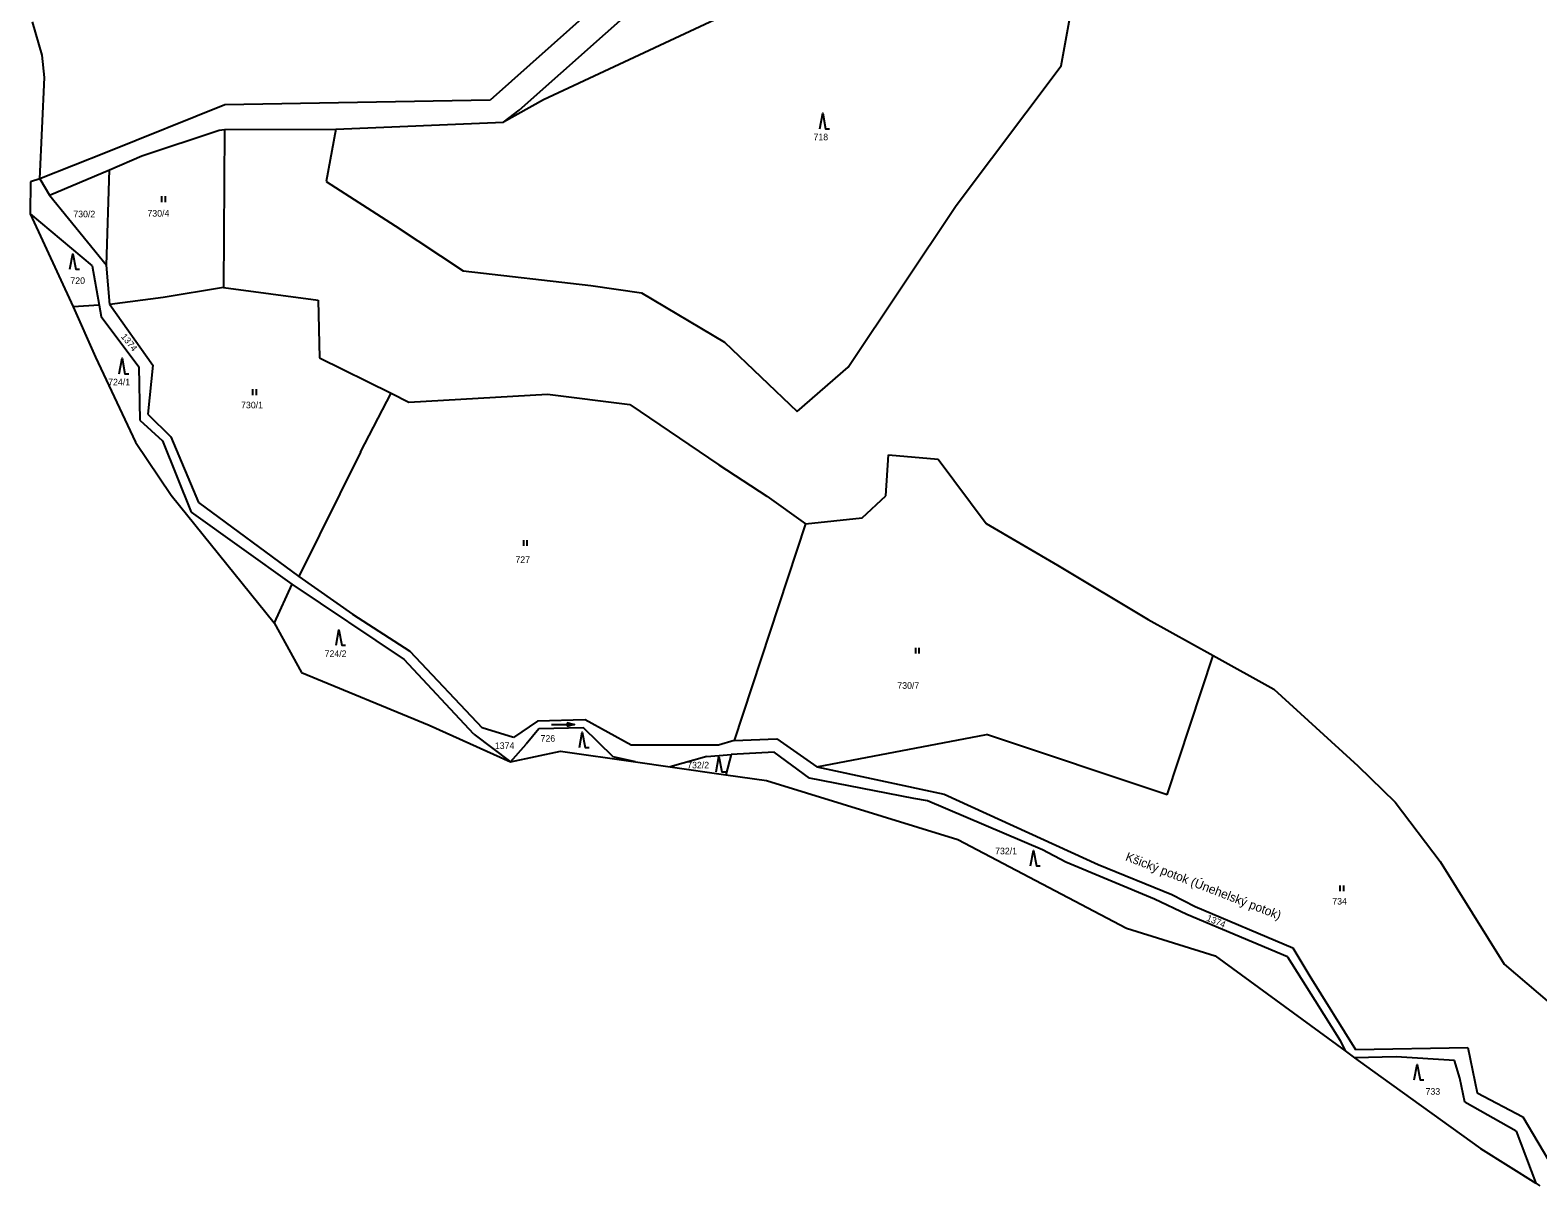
# Model space of a CAD drawing. Extents: x -845995 to -842497, y -1063614 to -1059680.
# Drawn here: x -845778.2 to -845387.3, y -1062481.6 to -1062182 of the extents above; entities that cross this region are included whole.
import ezdxf

# ---------------------------------------------------------------- set-up
doc = ezdxf.new("R2010")
doc.units = 0
for name, color, linetype in [('KN_HRANICE', 7, 'Continuous'), ('KN_KULTURY', 7, 'Continuous'), ('KN_PARCELY', 7, 'Continuous')]:
    doc.layers.add(name, color=color, linetype=linetype)

# ---------------------------------------------------------------- blocks, each defined once
blk = doc.blocks.new('306')
for p, q in [((-0.5, 1.5), (-0.5, 0)), ((0.5, 0), (0.5, 1.5))]:
    blk.add_line(p, q)
blk = doc.blocks.new('308')
blk.add_lwpolyline([(-0.75, 0), (0, 4), (0.75, 0), (1.75, 0)])
blk = doc.blocks.new('802')
blk.add_line((-3, 0), (3, 0))
blk.add_lwpolyline([(1, 0.5), (3, 0), (1, -0.5)])

msp = doc.modelspace()

# ---------------------------------------------------------------- linework, layer by layer
at = {"layer": 'KN_HRANICE'}
for p, q in [((-845510.92, -1062191.27), (-845498.56, -1062124.27)), ((-845651.42, -1062202.77), (-845618.23, -1062173.22)), ((-845585.39, -1062172.12), (-845645.11, -1062200.07)), ((-845632.82, -1062176.92), (-845658.96, -1062200.15)), ((-845775.06, -1062188.48), (-845777.6, -1062179.8)), ((-845774.46, -1062194.26), (-845775.06, -1062188.48)), ((-845775.65, -1062220.58), (-845774.46, -1062194.26)), ((-845538.14, -1062227.46), (-845510.92, -1062191.27)), ((-845727.72, -1062201.4), (-845758.25, -1062213.62)), ((-845658.96, -1062200.15), (-845727.72, -1062201.4)), ((-845645.11, -1062200.07), (-845655.45, -1062205.83)), ((-845698.95, -1062207.66), (-845655.45, -1062205.83)), ((-845655.45, -1062205.83), (-845651.42, -1062202.77)), ((-845749.23, -1062214.6), (-845729.21, -1062207.92)), ((-845729.21, -1062207.92), (-845727.82, -1062207.78)), ((-845727.82, -1062207.78), (-845728.1, -1062248.74)), ((-845727.82, -1062207.78), (-845698.95, -1062207.66)), ((-845698.95, -1062207.66), (-845701.42, -1062221.27)), ((-845758.25, -1062213.62), (-845775.65, -1062220.58)), ((-845757.67, -1062218.18), (-845749.23, -1062214.6)), ((-845778.11, -1062221.36), (-845778.2, -1062229.6)), ((-845775.65, -1062220.58), (-845778.11, -1062221.36)), ((-845775.65, -1062220.58), (-845773.15, -1062224.75)), ((-845773.15, -1062224.75), (-845757.67, -1062218.18)), ((-845758.41, -1062242.97), (-845757.67, -1062218.18)), ((-845701.42, -1062221.27), (-845683.57, -1062232.73)), ((-845773.15, -1062224.75), (-845758.41, -1062242.97)), ((-845778.2, -1062229.6), (-845767.01, -1062253.72)), ((-845778.2, -1062229.6), (-845762.16, -1062243.11)), ((-845566.08, -1062269.34), (-845538.14, -1062227.46)), ((-845683.57, -1062232.73), (-845665.91, -1062244.39)), ((-845762.16, -1062243.11), (-845760.29, -1062253.3)), ((-845757.58, -1062253.13), (-845758.41, -1062242.97)), ((-845665.91, -1062244.39), (-845632.86, -1062248.21)), ((-845728.1, -1062248.74), (-845743.72, -1062251.32)), ((-845728.1, -1062248.74), (-845703.56, -1062252.04)), ((-845632.86, -1062248.21), (-845619.68, -1062250.08)), ((-845743.72, -1062251.32), (-845757.58, -1062253.13)), ((-845757.58, -1062253.13), (-845746.37, -1062268.87)), ((-845703.56, -1062252.04), (-845703.22, -1062266.93)), ((-845619.68, -1062250.08), (-845598.19, -1062262.9)), ((-845760.29, -1062253.3), (-845767.01, -1062253.72)), ((-845767.01, -1062253.72), (-845761.26, -1062266.79)), ((-845760.29, -1062253.3), (-845759.76, -1062256.21)), ((-845759.76, -1062256.21), (-845750.05, -1062269.33)), ((-845598.19, -1062262.9), (-845579.34, -1062280.85)), ((-845761.26, -1062266.79), (-845750.91, -1062288.83)), ((-845746.37, -1062268.87), (-845747.73, -1062281.56)), ((-845703.22, -1062266.93), (-845684.57, -1062276.13)), ((-845750.05, -1062269.33), (-845749.77, -1062283.12)), ((-845579.34, -1062280.85), (-845566.08, -1062269.34)), ((-845692.53, -1062291.38), (-845684.57, -1062276.13)), ((-845684.57, -1062276.13), (-845680, -1062278.42)), ((-845680, -1062278.42), (-845644.04, -1062276.4)), ((-845644.04, -1062276.4), (-845622.69, -1062279.09)), ((-845622.69, -1062279.09), (-845599.61, -1062294.67)), ((-845749.77, -1062283.12), (-845743.88, -1062288.46)), ((-845747.73, -1062281.56), (-845741.76, -1062287.4)), ((-845741.76, -1062287.4), (-845734.56, -1062304.48)), ((-845750.91, -1062288.83), (-845741.6, -1062302.55)), ((-845743.88, -1062288.46), (-845736.47, -1062306.95)), ((-845692.53, -1062291.38), (-845708.51, -1062323.62)), ((-845556.32, -1062302.73), (-845555.68, -1062292.15)), ((-845555.68, -1062292.15), (-845542.82, -1062293.26)), ((-845599.61, -1062294.67), (-845587.21, -1062302.86)), ((-845542.82, -1062293.26), (-845530.36, -1062309.89)), ((-845741.6, -1062302.55), (-845714.94, -1062335.63)), ((-845587.21, -1062302.86), (-845577.18, -1062310.01)), ((-845562.49, -1062308.46), (-845556.32, -1062302.73)), ((-845736.47, -1062306.95), (-845710.33, -1062325.65)), ((-845734.56, -1062304.48), (-845708.51, -1062323.62)), ((-845577.18, -1062310.01), (-845595.64, -1062366.15)), ((-845577.18, -1062310.01), (-845562.49, -1062308.46)), ((-845530.36, -1062309.89), (-845511.8, -1062320.74)), ((-845511.8, -1062320.74), (-845488.37, -1062334.79)), ((-845710.33, -1062325.65), (-845714.94, -1062335.63)), ((-845710.33, -1062325.65), (-845681.19, -1062345.2)), ((-845708.51, -1062323.62), (-845694.59, -1062333.41)), ((-845694.59, -1062333.41), (-845679.72, -1062342.99)), ((-845488.37, -1062334.79), (-845471.52, -1062344.14)), ((-845714.94, -1062335.63), (-845707.89, -1062348.59)), ((-845679.72, -1062342.99), (-845661.03, -1062362.87)), ((-845663.13, -1062364.51), (-845681.19, -1062345.2)), ((-845483.41, -1062380.25), (-845471.52, -1062344.14)), ((-845471.52, -1062344.14), (-845455.72, -1062352.91)), ((-845707.89, -1062348.59), (-845674.77, -1062362.22)), ((-845455.72, -1062352.91), (-845433.95, -1062372.78)), ((-845674.77, -1062362.22), (-845653.62, -1062371.73)), ((-845646.63, -1062361.15), (-845652.9, -1062365.37)), ((-845634.27, -1062360.83), (-845646.63, -1062361.15)), ((-845622.41, -1062367.4), (-845634.27, -1062360.83)), ((-845663.13, -1062364.51), (-845653.62, -1062371.73)), ((-845652.9, -1062365.37), (-845661.03, -1062362.87)), ((-845646.29, -1062363.18), (-845649.61, -1062367.17)), ((-845634.77, -1062362.87), (-845646.29, -1062363.18)), ((-845627.07, -1062370.42), (-845634.77, -1062362.87)), ((-845595.64, -1062366.15), (-845599.71, -1062367.4)), ((-845595.64, -1062366.15), (-845584.65, -1062365.74)), ((-845584.65, -1062365.74), (-845574.23, -1062373.03)), ((-845574.23, -1062373.03), (-845530.28, -1062364.66)), ((-845483.41, -1062380.25), (-845530.28, -1062364.66)), ((-845653.62, -1062371.73), (-845649.61, -1062367.17)), ((-845653.62, -1062371.73), (-845640.67, -1062368.93)), ((-845640.67, -1062368.93), (-845621.27, -1062371.71)), ((-845621.27, -1062371.71), (-845627.07, -1062370.42)), ((-845599.71, -1062367.4), (-845622.41, -1062367.4)), ((-845602.76, -1062370.37), (-845612.24, -1062373)), ((-845602.76, -1062370.37), (-845596.47, -1062369.79)), ((-845596.47, -1062369.79), (-845597.82, -1062375.07)), ((-845585.27, -1062369.17), (-845596.47, -1062369.79)), ((-845576.16, -1062375.93), (-845585.27, -1062369.17)), ((-845621.27, -1062371.71), (-845612.24, -1062373)), ((-845612.24, -1062373), (-845597.82, -1062375.07)), ((-845574.23, -1062373.03), (-845541.21, -1062380.09)), ((-845433.95, -1062372.78), (-845424.34, -1062382.17)), ((-845597.82, -1062375.07), (-845587.27, -1062376.58)), ((-845587.27, -1062376.58), (-845537.67, -1062391.86)), ((-845549.1, -1062381.25), (-845576.16, -1062375.93)), ((-845545.53, -1062381.85), (-845549.1, -1062381.25)), ((-845515.71, -1062394.53), (-845545.53, -1062381.85)), ((-845541.21, -1062380.09), (-845501.27, -1062398.35)), ((-845424.34, -1062382.17), (-845412.62, -1062397.55)), ((-845537.67, -1062391.86), (-845493.94, -1062414.8)), ((-845509.64, -1062397.72), (-845515.71, -1062394.53)), ((-845486.73, -1062407.28), (-845509.64, -1062397.72)), ((-845412.62, -1062397.55), (-845396.08, -1062424.17)), ((-845501.27, -1062398.35), (-845482.18, -1062406.14)), ((-845478.34, -1062411.29), (-845486.73, -1062407.28)), ((-845482.18, -1062406.14), (-845476.17, -1062409.26)), ((-845476.17, -1062409.26), (-845450.8, -1062419.96)), ((-845452.19, -1062422.25), (-845478.34, -1062411.29)), ((-845493.94, -1062414.8), (-845471, -1062422.01)), ((-845450.8, -1062419.96), (-845446.45, -1062427.27)), ((-845471, -1062422.01), (-845437.29, -1062446.65)), ((-845452.19, -1062422.25), (-845445.13, -1062433.49)), ((-845396.08, -1062424.17), (-845369.78, -1062446.61)), ((-845446.45, -1062427.27), (-845434.59, -1062446.32)), ((-845445.13, -1062433.49), (-845438.53, -1062443.97)), ((-845438.53, -1062443.97), (-845437.29, -1062446.65)), ((-845437.29, -1062446.65), (-845434.86, -1062448.43)), ((-845424.05, -1062448.21), (-845434.86, -1062448.43)), ((-845434.86, -1062448.43), (-845430.15, -1062451.87)), ((-845434.59, -1062446.32), (-845405.42, -1062445.77)), ((-845408.94, -1062449.19), (-845424.05, -1062448.21)), ((-845405.42, -1062445.77), (-845403.08, -1062457.49)), ((-845430.15, -1062451.87), (-845402.15, -1062471.99)), ((-845407.5, -1062453.75), (-845408.94, -1062449.19)), ((-845406.21, -1062459.97), (-845407.5, -1062453.75)), ((-845392.93, -1062467.49), (-845406.21, -1062459.97)), ((-845403.08, -1062457.49), (-845391.23, -1062463.78)), ((-845391.23, -1062463.78), (-845383.43, -1062476.87)), ((-845392.93, -1062467.49), (-845387.84, -1062480.98)), ((-845402.15, -1062471.99), (-845387.84, -1062480.98)), ((-845387.84, -1062480.98), (-845386.77, -1062481.65))]:
    msp.add_line(p, q, dxfattribs=at)

# ---------------------------------------------------------------- block references
at = {"layer": 'KN_KULTURY'}
for name, p in [('308', (-845572.72, -1062207.56)), ('306', (-845743.63, -1062226.57)), ('308', (-845767.15, -1062244.01)), ('308', (-845754.36, -1062271.08)), ('306', (-845720.03, -1062276.6)), ('306', (-845649.82, -1062315.71)), ('308', (-845698.15, -1062341.5)), ('306', (-845548.18, -1062343.64)), ('802', (-845640.07, -1062362.03)), ('308', (-845635.05, -1062367.98)), ('308', (-845599.61, -1062374.34)), ('308', (-845518.06, -1062398.71)), ('306', (-845438.1, -1062405.26)), ('308', (-845418.59, -1062454.15))]:
    msp.add_blockref(name, p, dxfattribs=at)

# ---------------------------------------------------------------- texts
at = {"layer": 'KN_PARCELY'}
for s, p in [('718', (-845575.11, -1062210.54)), ('730/2', (-845767.01, -1062230.52)), ('730/4', (-845747.8, -1062230.35)), ('720', (-845767.77, -1062247.8)), ('724/1', (-845757.98, -1062274.09)), ('730/1', (-845723.52, -1062280.05)), ('727', (-845652.39, -1062320.14)), ('724/2', (-845701.86, -1062344.52)), ('730/7', (-845553.37, -1062352.77)), ('726', (-845645.87, -1062366.49)), ('1374', (-845657.72, -1062368.37)), ('732/2', (-845607.86, -1062373.41)), ('732/1', (-845528.02, -1062395.68)), ('734', (-845440.6, -1062408.71)), ('733', (-845416.42, -1062458.02))]:
    msp.add_text(s, height=1.7, dxfattribs=at).set_placement(p)
for s, height, rotation, p in [('1374', 1.7, 308.767, (-845754.76, -1062261.5)), ('Kšický potok (Únehelský potok)', 2.3, 338.847, (-845494.41, -1062397.19)), ('1374', 1.7, 337.472, (-845473.37, -1062412.85))]:
    msp.add_text(s, height=height, rotation=rotation, dxfattribs=at).set_placement(p)

doc.saveas('drawing.dxf')
